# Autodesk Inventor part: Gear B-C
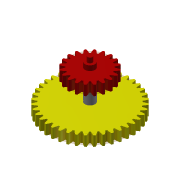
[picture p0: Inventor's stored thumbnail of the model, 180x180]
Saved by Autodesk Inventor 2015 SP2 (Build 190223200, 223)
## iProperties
Created: 2019-12
Part Number: Gear B-C
Material: 一般
Document SubType Name: Modeling
Designer: Kuan_Lun Hsu
Density: 1 g/cm^3
Appearance: 預設
Mass: 64.9746 g
Surface Area: 210.223 cm^2
Volume: 64.9746 cm^3
Author: Kuan_Lun Hsu
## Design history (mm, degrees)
derived "Gear B-C.iam"
sketch "草圖2"
  geometry: C1 r 5 at (0, 0) reference; 1 further point
extrude "擠出1" join sketch "草圖2" stored distance "d1" = 10; taper "d2" = 0 deg
node "實體1"
node "Spur Gear1:1"
node "曲面1"
node "Spur Gear2:1"
node "曲面2"
feature "曲面2::導出"
feature "曲面2::導出_1"
